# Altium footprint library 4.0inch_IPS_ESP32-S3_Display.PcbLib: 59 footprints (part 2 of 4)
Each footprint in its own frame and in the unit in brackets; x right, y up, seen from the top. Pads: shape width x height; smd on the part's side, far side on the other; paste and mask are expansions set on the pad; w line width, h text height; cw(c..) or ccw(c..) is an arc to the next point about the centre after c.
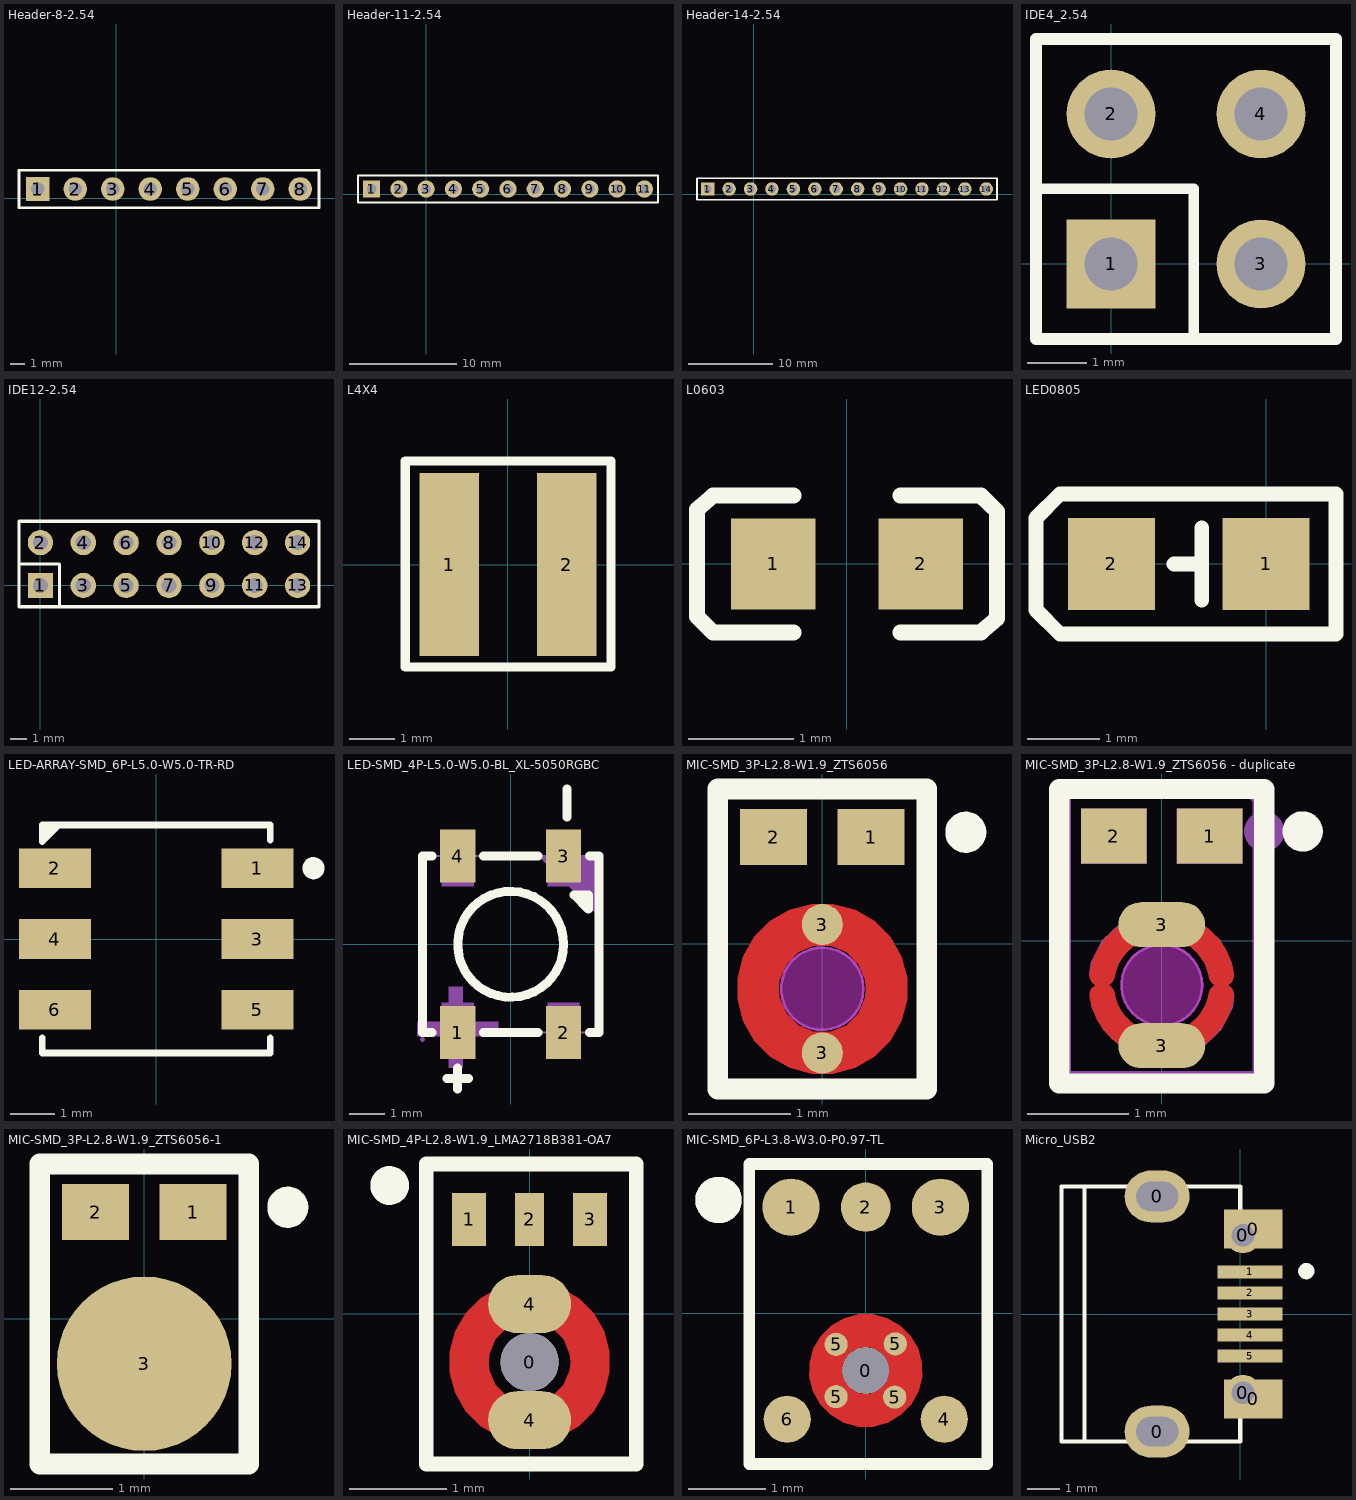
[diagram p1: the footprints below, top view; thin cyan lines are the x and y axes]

## Header-8-2.54 [mm] "header 8 pin"
pads (8):
  rect 1.6x1.6 hole 0.9: 1(-5.334,0.635)
  round 1.6 hole 0.9: 2(-2.794,0.635) 3(-0.254,0.635) 4(2.286,0.635) 5(4.826,0.635) 6(7.366,0.635) 7(9.906,0.635) 8(12.446,0.635)
Top Overlay:
  lines w0.203: -6.603,-0.635 -6.603,1.905 13.717,1.905 13.717,-0.635 -6.603,-0.635

## Header-11-2.54 [mm] "header 11 pin"
pads (11):
  rect 1.6x1.6 hole 0.9: 1(-5.08,0.508)
  round 1.6 hole 0.9: 2(-2.54,0.508) 3(0,0.508) 4(2.54,0.508) 5(5.08,0.508) 6(7.62,0.508) 7(10.16,0.508) 8(12.7,0.508) 9(15.24,0.508) 10(17.78,0.508) 11(20.32,0.508)
Top Overlay:
  lines w0.203: -6.349,-0.762 -6.349,1.778 21.591,1.778 21.591,-0.762 -6.349,-0.762

## Header-14-2.54 [mm] "header 14 pin"
pads (14):
  rect 1.6x1.6 hole 0.9: 1(-5.461,0.635)
  round 1.6 hole 0.9: 2(-2.921,0.635) 3(-0.381,0.635) 4(2.159,0.635) 5(4.699,0.635) 6(7.239,0.635) 7(9.779,0.635) 8(12.319,0.635) 9(14.859,0.635) 10(17.399,0.635) 11(19.939,0.635) 12(22.479,0.635) 13(25.019,0.635) 14(27.559,0.635)
Top Overlay:
  lines w0.203: -6.73,-0.635 28.83,-0.635 28.83,1.905 -6.73,1.905 -6.73,-0.635

## IDE4_2.54 [mm]
pads (4):
  rect 1.5x1.5 hole 0.9: 1(0,0)
  round 1.5 hole 0.9: 2(0,2.54) 3(2.54,0) 4(2.54,2.54)
Top Overlay:
  lines w0.178: -1.27,1.27 1.397,1.27 1.397,-1.27
  lines w0.2: -1.27,-1.27 -1.27,3.81 3.81,3.81 3.81,-1.27 -1.27,-1.27

## IDE12-2.54 [mm]
pads (14):
  rect 1.5x1.5 hole 0.9: 1(0,0)
  round 1.5 hole 0.9: 2(0,2.54) 3(2.54,0) 4(2.54,2.54) 5(5.08,0) 6(5.08,2.54) 7(7.62,0) 8(7.62,2.54) 9(10.16,0) 10(10.16,2.54) 11(12.7,0) 12(12.7,2.54) 13(15.24,0) 14(15.24,2.54)
Top Overlay:
  lines w0.178: -1.27,1.27 1.143,1.27 1.143,-1.27
  lines w0.2: -1.27,-1.27 16.51,-1.27 16.51,3.81 -1.27,3.81 -1.27,-1.27

## L4X4 [mm]
pads (2):
  rect 1.3x4 smd: 1(-1.279,0) 2(1.28,0)
Top Overlay:
  lines w0.2: -2.245,-2.235 2.255,-2.235 2.255,2.265 -2.245,2.265 -2.245,-2.235
3D body "L4x4.STEP": height 1, standoff -0.02, extent -2,-2 2,2

## L0603 [mm]
pads (2):
  rect 0.8x0.864 smd paste-100 mask+0.051: 1(-0.7,0) 2(0.7,0)
Top Overlay:
  lines w0.152: -1.272,-0.65 -0.51,-0.65 ; -1.272,0.65 -0.51,0.65 ; -1.27,-0.651 -1.424,-0.499 -1.424,0.517 -1.27,0.65 ; 0.51,-0.65 1.272,-0.65 ; 0.51,0.65 1.272,0.65 ; 1.27,-0.65 1.424,-0.517 1.424,0.499 1.27,0.65
3D body "User Library-Fast Acting Surface-Mount Fuses.STEP": height 0.8, standoff 0, extent -0.794,-0.407 0.806,0.395

## LED0805 [mm]
pads (2):
  rect 1.2x1.27 smd: 1(0,0) 2(-2.134,0)
Top Overlay:
  lines w0.203: -1.27,0 -0.889,0 ; -0.889,-0.5 -0.889,0.5 ; -3.175,-0.635 -2.845,-0.965 -2.794,-0.965 0.965,-0.965 0.965,0.965 -2.845,0.965 -3.175,0.635 -3.175,-0.635

## LED-ARRAY-SMD_6P-L5.0-W5.0-TR-RD [mm]
pads (6):
  rect 1.625x0.896 smd mask+0.051: 1(2.288,1.6) 2(-2.288,1.6) 3(2.288,0) 4(-2.288,0) 5(2.288,-1.6) 6(-2.288,-1.6)
Top Overlay:
  circle w0.25: c3.556,1.6 r0.125
  region: -2.54,2.159 -2.54,2.202 -2.576,2.239
  region: -2.286,2.576 -2.576,2.576 -2.576,2.239 -2.497,2.239 -2.159,2.576
  lines w0.152: -2.576,-2.239 -2.576,-2.576 2.576,-2.576 2.576,-2.239 ; -2.202,2.576 -2.576,2.202 -2.576,2.576 2.576,2.576 2.576,2.239

## LED-SMD_4P-L5.0-W5.0-BL_XL-5050RGBC [mm]
pads (4):
  rect 1x1.5 smd: 1(-1.5,-2.5) 2(1.5,-2.5) 3(1.5,2.5) 4(-1.5,2.5)
Top Overlay:
  circle w0.254: c0,-0.001 r1.5
  lines w0.254: -2.23,-2.501 -2.5,-2.501 -2.5,2.499 -2.23,2.499 ; -1.8,-3.8 -1.2,-3.8 ; -1.5,-4.1 -1.5,-3.5 ; -0.77,-2.501 0.77,-2.501 ; -0.77,2.499 0.77,2.499 ; 1.6,3.6 1.6,4.4 ; 2.23,-2.501 2.5,-2.501 2.5,2.499 2.23,2.499 ; 1.8,1.399 2.2,0.999 2.2,1.399 1.8,1.399
Mechanical 6:
  region: 0.9,2.5 0.8,2.5 0.9,2.4 2.5,0.8 2.5,2.5
  region: -1.75,-3.5 -1.75,-1.2 -1.45,-1.2 -1.35,-1.2 -1.35,-1.3 -1.35,-3.5
  region: -2.65,-2.2 -2.65,-2.6 -0.35,-2.6 -0.35,-2.2
Mechanical 15:
  region: 1.95,2.7 1.95,1.65 1.05,1.65 1.05,2.7
  region: 1.95,-1.65 1.95,-2.7 1.05,-2.7 1.05,-1.65
  region: -1.05,-1.65 -1.05,-2.7 -1.95,-2.7 -1.95,-1.65
  region: -1.05,2.7 -1.05,1.65 -1.95,1.65 -1.95,2.7
  region: -2.44,-2.7 -2.44,-2.675 -2.475,-2.64 -2.525,-2.64 -2.56,-2.675 -2.56,-2.7 -2.56,-2.725 -2.525,-2.76 -2.475,-2.76 -2.44,-2.725
  lines w0.051: -2.5,-2.5 2.5,-2.5 2.5,2.5 -2.5,2.5 -2.5,-2.5
3D body "User Library-ws2812B-1.STEP": height 1.5, standoff -0.07, extent -2.534,-2.978 2.466,2.422

## MIC-SMD_3P-L2.8-W1.9_ZTS6056 [mm]
pads (4):
  rect 0.65x0.545 smd paste-100 mask+0.051: 1(0.475,1.039) 2(-0.475,1.039)
  round 0.4 smd: 3(0,-1.064) 3(0,0.186)
Top Layer:
  region: -0.825,-0.439 -0.825,-0.547 -0.769,-0.757 -0.66,-0.945 -0.507,-1.099 -0.318,-1.208 -0.109,-1.264 0.109,-1.264 0.318,-1.208 0.507,-1.099 0.66,-0.945 0.769,-0.757 0.825,-0.547 0.825,-0.439 0.425,-0.439 0.417,-0.522 0.353,-0.675 0.236,-0.792 0.083,-0.856 -0.083,-0.856 -0.236,-0.792 -0.353,-0.675 -0.417,-0.522 -0.425,-0.439
  region: -0.825,-0.439 -0.825,-0.33 -0.769,-0.12 -0.66,0.068 -0.507,0.221 -0.318,0.33 -0.109,0.386 0.109,0.386 0.318,0.33 0.507,0.221 0.66,0.068 0.769,-0.12 0.825,-0.33 0.825,-0.439 0.425,-0.439 0.417,-0.356 0.353,-0.203 0.236,-0.085 0.083,-0.022 -0.083,-0.022 -0.236,-0.085 -0.353,-0.203 -0.417,-0.356 -0.425,-0.439
Top Overlay:
  circle w0.2: c1.397,1.085 r0.1
  lines w0.2: -1.016,-1.415 1.016,-1.415 1.016,1.506 -1.016,1.506 -1.016,-1.415
Top Paste:
  region: -0.8,1.311 -0.15,1.311 -0.15,0.766 -0.8,0.766
  region: 0.15,1.311 0.8,1.311 0.8,0.766 0.15,0.766
  region: -0.825,-0.439 -0.825,-0.33 -0.769,-0.12 -0.66,0.068 -0.507,0.221 -0.318,0.33 -0.109,0.386 0.109,0.386 0.318,0.33 0.507,0.221 0.66,0.068 0.769,-0.12 0.825,-0.33 0.825,-0.439 0.425,-0.439 0.417,-0.356 0.353,-0.203 0.236,-0.085 0.083,-0.022 -0.083,-0.022 -0.236,-0.085 -0.353,-0.203 -0.417,-0.356 -0.425,-0.439
  region: -0.825,-0.439 -0.825,-0.547 -0.769,-0.757 -0.66,-0.945 -0.507,-1.099 -0.318,-1.208 -0.109,-1.264 0.109,-1.264 0.318,-1.208 0.507,-1.099 0.66,-0.945 0.769,-0.757 0.825,-0.547 0.825,-0.439 0.425,-0.439 0.417,-0.522 0.353,-0.675 0.236,-0.792 0.083,-0.856 -0.083,-0.856 -0.236,-0.792 -0.353,-0.675 -0.417,-0.522 -0.425,-0.439
Top Solder:
  region: -0.825,-0.439 -0.825,-0.33 -0.769,-0.12 -0.66,0.068 -0.507,0.221 -0.318,0.33 -0.109,0.386 0.109,0.386 0.318,0.33 0.507,0.221 0.66,0.068 0.769,-0.12 0.825,-0.33 0.825,-0.439 0.425,-0.439 0.417,-0.356 0.353,-0.203 0.236,-0.085 0.083,-0.022 -0.083,-0.022 -0.236,-0.085 -0.353,-0.203 -0.417,-0.356 -0.425,-0.439
  region: -0.825,-0.439 -0.825,-0.547 -0.769,-0.757 -0.66,-0.945 -0.507,-1.099 -0.318,-1.208 -0.109,-1.264 0.109,-1.264 0.318,-1.208 0.507,-1.099 0.66,-0.945 0.769,-0.757 0.825,-0.547 0.825,-0.439 0.425,-0.439 0.417,-0.522 0.353,-0.675 0.236,-0.792 0.083,-0.856 -0.083,-0.856 -0.236,-0.792 -0.353,-0.675 -0.417,-0.522 -0.425,-0.439
Keep-Out Layer:
  board cut-out: 0.4,-0.439 0.399,-0.36 0.336,-0.216 0.224,-0.105 0.079,-0.046 -0.079,-0.046 -0.224,-0.105 -0.337,-0.216 -0.399,-0.36 -0.4,-0.439 -0.399,-0.517 -0.337,-0.662 -0.224,-0.772 -0.079,-0.832 0.079,-0.832 0.224,-0.772 0.336,-0.662 0.399,-0.517
Keep-Out Layer:
  circle w0.025: c0,-0.439 r0.4
Mechanical 1:
  circle w0.025: c0,-0.439 r0.4

## MIC-SMD_3P-L2.8-W1.9_ZTS6056 - duplicate [mm]
pads (4):
  rect 0.65x0.545 smd paste-100 mask+0.051: 1(0.475,1.039) 2(-0.475,1.039)
  oval 0.859x0.447 smd: 3(0,-1.039) 3(0,0.161)
Top Layer:
  region: -0.468,-0.521 -0.461,-0.552 -0.453,-0.583 -0.442,-0.612 -0.43,-0.641 -0.415,-0.669 -0.399,-0.696 -0.381,-0.722 -0.361,-0.747 -0.34,-0.77 -0.317,-0.792 -0.293,-0.813 -0.268,-0.831 -0.241,-0.848 -0.213,-0.863 -0.185,-0.876 -0.155,-0.888 -0.125,-0.897 -0.094,-0.904 -0.063,-0.91 -0.032,-0.913 0,-0.914 0.032,-0.913 0.063,-0.91 0.094,-0.904 0.125,-0.897 0.155,-0.888 0.184,-0.876 0.213,-0.863 0.241,-0.848 0.268,-0.831 0.293,-0.813 0.317,-0.792 0.34,-0.77 0.361,-0.747 0.381,-0.722 0.399,-0.696 0.415,-0.669 0.43,-0.641 0.442,-0.612 0.453,-0.583 0.461,-0.552 0.468,-0.521 0.472,-0.505 0.478,-0.49 0.485,-0.476 0.495,-0.463 0.506,-0.451 0.519,-0.441 0.533,-0.432 0.548,-0.425 0.564,-0.421 0.58,-0.418 0.596,-0.418 0.613,-0.42 0.628,-0.424 0.644,-0.43 0.658,-0.438 0.671,-0.447 0.683,-0.458 0.693,-0.471 0.702,-0.485 0.708,-0.5 0.713,-0.516 0.715,-0.532 0.716,-0.548 0.714,-0.565 0.706,-0.603 0.696,-0.64 0.685,-0.678 0.671,-0.714 0.655,-0.75 0.637,-0.784 0.618,-0.818 0.597,-0.851 0.574,-0.882 0.549,-0.912 0.523,-0.941 0.495,-0.968 0.466,-0.994 0.436,-1.018 0.404,-1.041 0.371,-1.062 0.337,-1.081 0.302,-1.098 0.266,-1.113 0.23,-1.126 0.192,-1.138 0.155,-1.147 0.116,-1.154 0.078,-1.16 0.039,-1.163 0,-1.164 -0.039,-1.163 -0.078,-1.16 -0.116,-1.154 -0.155,-1.147 -0.192,-1.138 -0.23,-1.126 -0.266,-1.113 -0.302,-1.098 -0.337,-1.081 -0.371,-1.062 -0.404,-1.041 -0.436,-1.018 -0.466,-0.994 -0.495,-0.968 -0.523,-0.941 -0.549,-0.912 -0.574,-0.882 -0.597,-0.851 -0.618,-0.818 -0.637,-0.784 -0.655,-0.75 -0.671,-0.714 -0.685,-0.678 -0.696,-0.64 -0.706,-0.603 -0.714,-0.565 -0.716,-0.548 -0.715,-0.532 -0.713,-0.516 -0.708,-0.5 -0.702,-0.485 -0.693,-0.471 -0.683,-0.458 -0.671,-0.447 -0.658,-0.438 -0.644,-0.43 -0.628,-0.424 -0.613,-0.42 -0.596,-0.418 -0.58,-0.418 -0.564,-0.421 -0.548,-0.425 -0.533,-0.432 -0.519,-0.441 -0.506,-0.451 -0.495,-0.463 -0.485,-0.476 -0.478,-0.49 -0.472,-0.505
  region: 0.468,-0.356 0.461,-0.325 0.453,-0.295 0.442,-0.265 0.43,-0.236 0.415,-0.208 0.399,-0.181 0.381,-0.155 0.361,-0.13 0.34,-0.107 0.317,-0.085 0.293,-0.065 0.268,-0.046 0.241,-0.029 0.213,-0.014 0.185,-0.001 0.155,0.01 0.125,0.02 0.094,0.027 0.063,0.032 0.032,0.035 0,0.036 -0.032,0.035 -0.063,0.032 -0.094,0.027 -0.125,0.02 -0.155,0.01 -0.185,-0.001 -0.213,-0.014 -0.241,-0.029 -0.268,-0.046 -0.293,-0.065 -0.317,-0.085 -0.34,-0.107 -0.361,-0.13 -0.381,-0.155 -0.399,-0.181 -0.415,-0.208 -0.43,-0.236 -0.442,-0.265 -0.453,-0.295 -0.461,-0.325 -0.468,-0.356 -0.472,-0.372 -0.478,-0.387 -0.485,-0.402 -0.495,-0.415 -0.506,-0.427 -0.519,-0.437 -0.533,-0.445 -0.548,-0.452 -0.564,-0.457 -0.58,-0.459 -0.596,-0.459 -0.613,-0.458 -0.628,-0.454 -0.644,-0.448 -0.658,-0.44 -0.671,-0.43 -0.683,-0.419 -0.693,-0.406 -0.702,-0.392 -0.708,-0.377 -0.713,-0.362 -0.715,-0.345 -0.716,-0.329 -0.714,-0.313 -0.706,-0.275 -0.696,-0.237 -0.685,-0.2 -0.671,-0.164 -0.655,-0.128 -0.637,-0.093 -0.618,-0.06 -0.597,-0.027 -0.574,0.005 -0.549,0.035 -0.523,0.063 -0.495,0.091 -0.466,0.117 -0.436,0.141 -0.404,0.163 -0.371,0.184 -0.337,0.203 -0.302,0.22 -0.266,0.236 -0.23,0.249 -0.192,0.26 -0.155,0.27 -0.116,0.277 -0.078,0.282 -0.039,0.285 0,0.286 0.039,0.285 0.078,0.282 0.116,0.277 0.155,0.27 0.192,0.26 0.23,0.249 0.266,0.236 0.302,0.22 0.337,0.203 0.371,0.184 0.404,0.163 0.436,0.141 0.466,0.117 0.495,0.091 0.523,0.063 0.549,0.035 0.574,0.005 0.597,-0.027 0.618,-0.06 0.637,-0.093 0.655,-0.128 0.671,-0.164 0.685,-0.2 0.696,-0.237 0.706,-0.275 0.714,-0.313 0.716,-0.329 0.715,-0.345 0.713,-0.362 0.708,-0.377 0.702,-0.392 0.693,-0.406 0.683,-0.419 0.671,-0.43 0.658,-0.44 0.644,-0.448 0.628,-0.454 0.613,-0.458 0.596,-0.459 0.58,-0.459 0.564,-0.457 0.548,-0.452 0.533,-0.445 0.519,-0.437 0.506,-0.427 0.495,-0.415 0.485,-0.402 0.478,-0.387 0.472,-0.372
Top Overlay:
  circle w0.2: c1.397,1.085 r0.1
  lines w0.2: -1.016,-1.415 -1.016,1.506 1.016,1.506 1.016,-1.415 -1.016,-1.415
Top Paste:
  region: 0.47,-0.539 0.72,-0.539 0.703,-0.662 0.59,-0.882 0.41,-1.053 0.184,-1.154 0.06,-1.164 -0.05,-1.164 -0.174,-1.154 -0.4,-1.053 -0.58,-0.882 -0.693,-0.662 -0.71,-0.539 -0.47,-0.539 -0.449,-0.61 -0.376,-0.738 -0.267,-0.838 -0.133,-0.899 -0.06,-0.914 0.06,-0.914 0.133,-0.899 0.267,-0.838 0.376,-0.738 0.449,-0.61
  region: -0.47,-0.339 -0.72,-0.339 -0.703,-0.216 -0.59,0.005 -0.41,0.175 -0.184,0.276 -0.06,0.286 0.05,0.286 0.174,0.276 0.4,0.175 0.58,0.005 0.693,-0.216 0.71,-0.339 0.47,-0.339 0.449,-0.268 0.376,-0.139 0.267,-0.039 0.133,0.022 0.06,0.036 -0.06,0.036 -0.133,0.022 -0.267,-0.039 -0.376,-0.139 -0.449,-0.268
  region: 0.15,1.311 0.8,1.311 0.8,0.766 0.15,0.766
  region: -0.8,1.311 -0.15,1.311 -0.15,0.766 -0.8,0.766
Keep-Out Layer:
  board cut-out: 0.4,-0.439 0.399,-0.36 0.336,-0.216 0.224,-0.105 0.079,-0.046 -0.079,-0.046 -0.224,-0.105 -0.337,-0.216 -0.399,-0.36 -0.4,-0.439 -0.399,-0.517 -0.337,-0.662 -0.224,-0.772 -0.079,-0.832 0.079,-0.832 0.224,-0.772 0.336,-0.662 0.399,-0.517
Keep-Out Layer:
  circle w0.025: c0,-0.439 r0.4
Mechanical 1:
  circle w0.025: c0,-0.439 r0.4
Mechanical 6:
  circle w0.2: c1.016,1.085 r0.1
Mechanical 15:
  region: 0.47,-0.539 0.72,-0.539 0.703,-0.662 0.59,-0.882 0.41,-1.053 0.184,-1.154 0.06,-1.164 -0.05,-1.164 -0.174,-1.154 -0.4,-1.053 -0.58,-0.882 -0.693,-0.662 -0.71,-0.539 -0.47,-0.539 -0.449,-0.61 -0.376,-0.738 -0.267,-0.838 -0.133,-0.899 -0.06,-0.914 0.06,-0.914 0.133,-0.899 0.267,-0.838 0.376,-0.738 0.449,-0.61
  region: -0.47,-0.339 -0.72,-0.339 -0.703,-0.216 -0.59,0.005 -0.41,0.175 -0.184,0.276 -0.06,0.286 0.05,0.286 0.174,0.276 0.4,0.175 0.58,0.005 0.693,-0.216 0.71,-0.339 0.47,-0.339 0.449,-0.268 0.376,-0.139 0.267,-0.039 0.133,0.022 0.06,0.036 -0.06,0.036 -0.133,0.022 -0.267,-0.039 -0.376,-0.139 -0.449,-0.268
  region: -0.8,1.311 -0.15,1.311 -0.15,0.766 -0.8,0.766
  region: 0.15,1.311 0.8,1.311 0.8,0.766 0.15,0.766
  region: 0.985,1.436 0.984,1.461 0.949,1.494 0.901,1.494 0.866,1.461 0.865,1.437 0.866,1.412 0.901,1.379 0.949,1.379 0.984,1.412
  lines w0.051: -0.925,-1.314 -0.925,1.436 0.925,1.436 0.925,-1.314 -0.925,-1.314

## MIC-SMD_3P-L2.8-W1.9_ZTS6056-1 [mm]
pads (3):
  rect 0.65x0.545 smd paste-100 mask+0.051: 1(0.475,1.039) 2(-0.475,1.039)
  round 1.7 smd mask+0.051: 3(0,-0.439)
Top Overlay:
  circle w0.2: c1.397,1.085 r0.1
  lines w0.2: -1.016,-1.415 1.016,-1.415 1.016,1.506 -1.016,1.506 -1.016,-1.415
Top Paste:
  region: -0.8,1.311 -0.15,1.311 -0.15,0.766 -0.8,0.766
  region: 0.15,1.311 0.8,1.311 0.8,0.766 0.15,0.766
Mechanical 1:
  circle w0.1: c0,-0.439 r0.4

## MIC-SMD_4P-L2.8-W1.9_LMA2718B381-OA7 [mm]
pads (6):
  round 0.6 hole 0.6 unplated mask+0.051: 0(0,-0.498)
  rect 0.35x0.55 smd paste-100 mask+0.051: 1(-0.625,0.977) 3(0.625,0.977)
  rect 0.3x0.55 smd paste-100 mask+0.051: 2(0,0.977)
  oval 0.859x0.6 smd mask+0.051: 4(0,-1.098) 4(0,0.102)
Top Layer:
  region: -0.825,-0.498 -0.825,-0.606 -0.769,-0.816 -0.66,-1.004 -0.506,-1.158 -0.318,-1.267 -0.109,-1.323 0.109,-1.323 0.319,-1.267 0.507,-1.158 0.66,-1.004 0.769,-0.816 0.825,-0.606 0.825,-0.498 0.425,-0.498 0.417,-0.581 0.353,-0.734 0.236,-0.851 0.083,-0.915 -0.083,-0.915 -0.236,-0.851 -0.353,-0.734 -0.417,-0.581 -0.425,-0.498
  region: -0.825,-0.498 -0.825,-0.389 -0.769,-0.179 -0.66,0.009 -0.506,0.162 -0.318,0.271 -0.109,0.327 0.109,0.327 0.319,0.271 0.507,0.162 0.66,0.009 0.769,-0.179 0.825,-0.389 0.825,-0.498 0.425,-0.498 0.417,-0.415 0.353,-0.262 0.236,-0.144 0.083,-0.081 -0.083,-0.081 -0.236,-0.144 -0.353,-0.262 -0.417,-0.415 -0.425,-0.498
Top Overlay:
  circle w0.2: c-1.447,1.327 r0.1
  lines w0.15: -1.07,-1.55 1.1,-1.55 1.1,1.55 -1.07,1.55 -1.07,-1.55
Top Paste:
  region: -0.825,-0.498 -0.825,-0.389 -0.769,-0.179 -0.66,0.009 -0.506,0.162 -0.318,0.271 -0.109,0.327 0.109,0.327 0.319,0.271 0.507,0.162 0.66,0.009 0.769,-0.179 0.825,-0.389 0.825,-0.498 0.425,-0.498 0.417,-0.415 0.353,-0.262 0.236,-0.144 0.083,-0.081 -0.083,-0.081 -0.236,-0.144 -0.353,-0.262 -0.417,-0.415 -0.425,-0.498
  region: -0.825,-0.498 -0.825,-0.606 -0.769,-0.816 -0.66,-1.004 -0.506,-1.158 -0.318,-1.267 -0.109,-1.323 0.109,-1.323 0.319,-1.267 0.507,-1.158 0.66,-1.004 0.769,-0.816 0.825,-0.606 0.825,-0.498 0.425,-0.498 0.417,-0.581 0.353,-0.734 0.236,-0.851 0.083,-0.915 -0.083,-0.915 -0.236,-0.851 -0.353,-0.734 -0.417,-0.581 -0.425,-0.498
Top Solder:
  region: -0.825,-0.498 -0.825,-0.389 -0.769,-0.179 -0.66,0.009 -0.506,0.162 -0.318,0.271 -0.109,0.327 0.109,0.327 0.319,0.271 0.507,0.162 0.66,0.009 0.769,-0.179 0.825,-0.389 0.825,-0.498 0.425,-0.498 0.417,-0.415 0.353,-0.262 0.236,-0.144 0.083,-0.081 -0.083,-0.081 -0.236,-0.144 -0.353,-0.262 -0.417,-0.415 -0.425,-0.498
  region: -0.825,-0.498 -0.825,-0.606 -0.769,-0.816 -0.66,-1.004 -0.506,-1.158 -0.318,-1.267 -0.109,-1.323 0.109,-1.323 0.319,-1.267 0.507,-1.158 0.66,-1.004 0.769,-0.816 0.825,-0.606 0.825,-0.498 0.425,-0.498 0.417,-0.581 0.353,-0.734 0.236,-0.851 0.083,-0.915 -0.083,-0.915 -0.236,-0.851 -0.353,-0.734 -0.417,-0.581 -0.425,-0.498
3D body "User Library-IM72D128V01XTMA1.STEP": height 1.2, standoff 0, extent -1.433,-2.041 1.567,1.959

## MIC-SMD_6P-L3.8-W3.0-P0.97-TL [mm]
pads (10):
  round 0.6 hole 0.6 unplated mask+0.051: 0(0,-0.74)
  round 0.74 smd paste+0 mask+0.05: 1(-0.965,1.37) 3(0.965,1.37)
  round 0.64 smd paste+0 mask+0.05: 2(0,1.37)
  round 0.61 smd paste+0 mask+0.05: 4(1.015,-1.37) 6(-1.015,-1.37)
  round 0.3 smd mask+0.051: 5(-0.384,-1.078) 5(-0.384,-0.404) 5(0.375,-1.083) 5(0.382,-0.396)
Top Layer:
  region: -0.725,-0.717 -0.728,-0.815 -0.682,-1.004 -0.588,-1.175 -0.453,-1.315 -0.285,-1.414 -0.097,-1.465 0.097,-1.465 0.285,-1.414 0.453,-1.315 0.588,-1.175 0.682,-1.004 0.728,-0.815 0.725,-0.717 0.304,-0.717 0.302,-0.78 0.261,-0.898 0.177,-0.989 0.062,-1.039 -0.062,-1.039 -0.177,-0.989 -0.261,-0.898 -0.302,-0.78 -0.304,-0.717
  region: 0.725,-0.74 0.725,-0.645 0.676,-0.46 0.58,-0.295 0.445,-0.16 0.28,-0.065 0.095,-0.015 -0.095,-0.015 -0.28,-0.065 -0.445,-0.16 -0.58,-0.295 -0.676,-0.46 -0.725,-0.645 -0.725,-0.74 -0.305,-0.74 -0.299,-0.681 -0.254,-0.571 -0.169,-0.487 -0.059,-0.441 0.06,-0.441 0.169,-0.487 0.254,-0.571 0.299,-0.681 0.305,-0.74
Top Overlay:
  circle w0.3: c-1.902,1.463 r0.15
  lines w0.15: -1.504,-1.948 -1.504,1.928 1.568,1.928 1.568,-1.948 -1.504,-1.948
Top Paste:
  region: 0.725,-0.74 0.725,-0.645 0.676,-0.46 0.58,-0.295 0.445,-0.16 0.28,-0.065 0.095,-0.015 -0.095,-0.015 -0.28,-0.065 -0.445,-0.16 -0.58,-0.295 -0.676,-0.46 -0.725,-0.645 -0.725,-0.74 -0.305,-0.74 -0.299,-0.681 -0.254,-0.571 -0.169,-0.487 -0.059,-0.441 0.06,-0.441 0.169,-0.487 0.254,-0.571 0.299,-0.681 0.305,-0.74
  region: -0.725,-0.717 -0.728,-0.815 -0.682,-1.004 -0.588,-1.175 -0.453,-1.315 -0.285,-1.414 -0.097,-1.465 0.097,-1.465 0.285,-1.414 0.453,-1.315 0.588,-1.175 0.682,-1.004 0.728,-0.815 0.725,-0.717 0.304,-0.717 0.302,-0.78 0.261,-0.898 0.177,-0.989 0.062,-1.039 -0.062,-1.039 -0.177,-0.989 -0.261,-0.898 -0.302,-0.78 -0.304,-0.717
Top Solder:
  region: 0.725,-0.74 0.725,-0.645 0.676,-0.46 0.58,-0.295 0.445,-0.16 0.28,-0.065 0.095,-0.015 -0.095,-0.015 -0.28,-0.065 -0.445,-0.16 -0.58,-0.295 -0.676,-0.46 -0.725,-0.645 -0.725,-0.74 -0.305,-0.74 -0.299,-0.681 -0.254,-0.571 -0.169,-0.487 -0.059,-0.441 0.06,-0.441 0.169,-0.487 0.254,-0.571 0.299,-0.681 0.305,-0.74
  region: -0.725,-0.717 -0.728,-0.815 -0.682,-1.004 -0.588,-1.175 -0.453,-1.315 -0.285,-1.414 -0.097,-1.465 0.097,-1.465 0.285,-1.414 0.453,-1.315 0.588,-1.175 0.682,-1.004 0.728,-0.815 0.725,-0.717 0.304,-0.717 0.302,-0.78 0.261,-0.898 0.177,-0.989 0.062,-1.039 -0.062,-1.039 -0.177,-0.989 -0.261,-0.898 -0.302,-0.78 -0.304,-0.717
Mechanical 6:
  circle w0.3: c-1.902,1.463 r0.15

## Micro_USB2 [mm] "Micro_USB Dock 5 Pin"
height 2.65
pads (11):
  oval 2x1.6 hole 0.9 slot 1.3 at 0 deg: 0(-2.564,-3.625) 0(-2.564,3.625)
  round 1.1 hole 0.7: 0(0.08,-2.425) 0(0.08,2.425)
  rect 1.8x1.2 smd: 0(0.4,-2.616) 0(0.4,2.616)
  rect 2x0.4 smd: 1(0.3,1.3) 2(0.3,0.65) 3(0.3,0) 4(0.3,-0.65) 5(0.3,-1.3)
Top Overlay:
  circle w0.25: c2.034,1.321 r0.125
  lines w0.127: -5.508,-3.937 -3.404,-3.937 ; -5.508,-3.9 -5.508,3.9 ; -5.508,3.937 -3.454,3.937 ; -4.809,-3.863 -4.809,3.937 ; -1.727,-3.937 0,-3.937 ; -1.651,3.937 0,3.937 ; 0,-3.9 0,-2.997 ; 0,2.972 0,3.9
3D body "User Library-MicroUSB-B_Molex_105017-0001.STEP": height 2.68, standoff -0.63, extent -5.201,-4.1 0.229,4.1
